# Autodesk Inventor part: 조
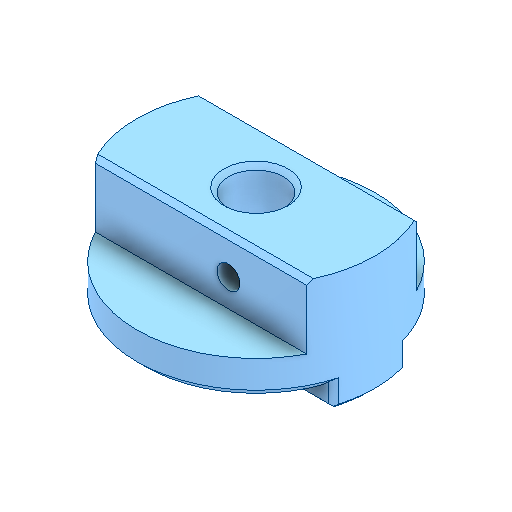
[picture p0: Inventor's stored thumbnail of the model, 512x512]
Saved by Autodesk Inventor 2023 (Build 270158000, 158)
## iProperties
Created: 2025-02
Part Number: 조
Material: 강철, 탄소
Document SubType Name: Modeling
Designer: home
Density: 7.85 g/cm^3
Appearance: 기본값
Author: jhkim
Sending System: Autodesk Inventor 2025
Preprocessor: ST-DEVELOPER v20
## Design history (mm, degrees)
node "조1"
node "솔리드2"
node "솔리드1"
